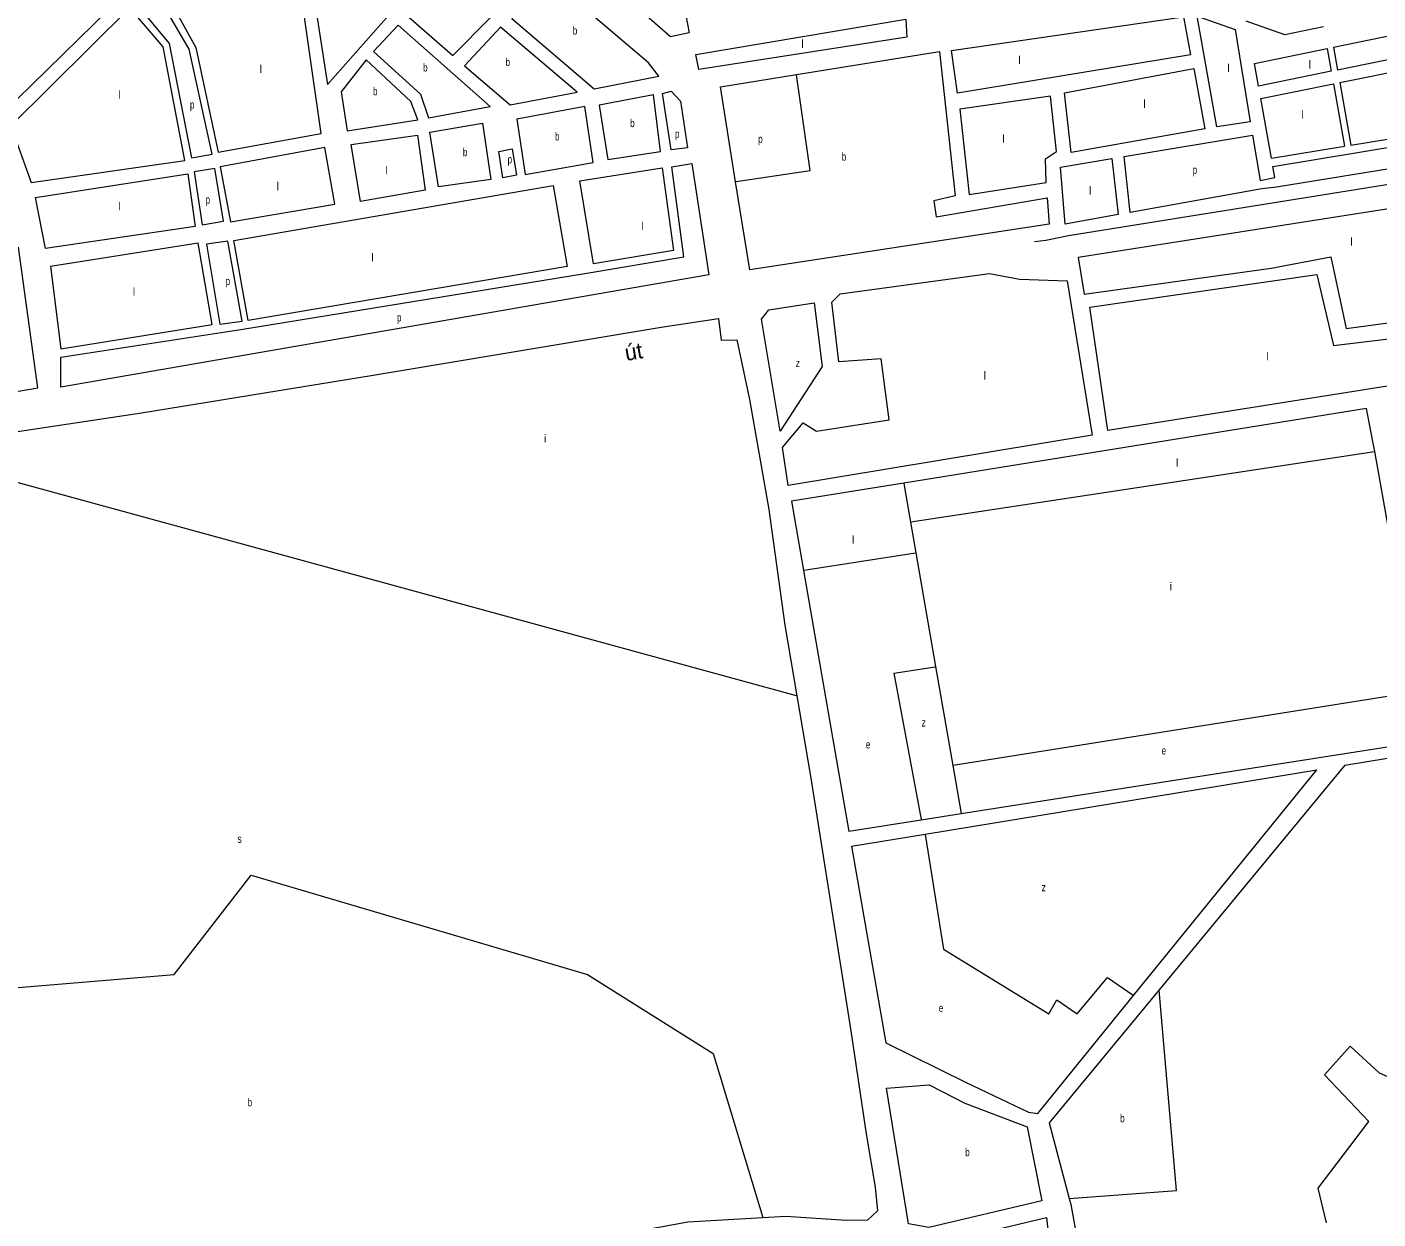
# Model space of a CAD drawing. Extents: x 639657 to 671642, y 222838 to 252123.
# Drawn here: x 655799 to 657488, y 238779 to 240268 of the extents above; entities that cross this region are included whole.
import ezdxf
from ezdxf.enums import TextEntityAlignment as Align

# ---------------------------------------------------------------- set-up
doc = ezdxf.new("R2010")
doc.units = 0
doc.header["$LTSCALE"] = 4
for name, color, linetype, lineweight in [('1', 7, 'Continuous', 13), ('21', 7, 'Continuous', 13), ('57', 7, 'Continuous', 35)]:
    doc.layers.add(name, color=color, linetype=linetype, lineweight=lineweight)
doc.layers.add('22', color=7, linetype='Continuous')
doc.layers.add('7', color=7, linetype='Continuous')

msp = doc.modelspace()

# ---------------------------------------------------------------- linework, layer by layer
at = {"layer": '1'}
for p, q in [((657440.128, 240199.175), (657810.98, 240273.89)), ((657432.386, 240243.339), (657437.407, 240214.696)), ((657424.384, 240241.691), (657429.422, 240213.067)), ((657429.422, 240213.067), (657338.5, 240194.51)), ((657432.149, 240197.567), (657445.911, 240119.373)), ((657440.128, 240199.175), (657453.886, 240120.68)), ((657356.452, 240094.294), (657868.995, 240179.025)), ((657453.886, 240120.68), (657863.625, 240187.808)), ((657354.638, 240104.42), (657445.911, 240119.373)), ((656620.345, 239981.002), (656605.174, 240093.516)), ((657358.975, 240080.212), (657356.452, 240094.294)), ((657340.768, 240076.569), (657358.975, 240080.212)), ((657532.85, 239461.56), (657483.794, 239737.856)), ((657446.404, 239345.829), (657548.961, 239362.665)), ((657076.74, 238898.92), (657101.809, 238804.075))]:
    msp.add_line(p, q, dxfattribs=at)
for points in [[(656038.26, 240112.12), (656167.07, 240135.24), (656138.48, 240333.32), (656161.37, 240359.31), (656024.31, 240480.17), (655954.37, 240424.76), (656018.37, 240359.19), (656046.1, 240384.68), (656055.85, 240376.7), (656017.48, 240338.22), (655942.63, 240414.45), (655887.738, 240364.976), (655929.677, 240318.542), (655946.632, 240334.615), (655986.76, 240284.75), (656010.24, 240243.03)], [(656184.46, 240361.66), (656331.27, 240232.83), (656378.16, 240279.98), (656227.04, 240410.92)], [(655875.92, 240357.99), (655708.83, 240222.76), (655766.91, 240158.75), (655921.49, 240310.54)], [(656155.79, 240320.57), (656174.61, 240196.57), (656251.27, 240283.21), (656174.37, 240347.6)], [(656004.633, 240105.124), (656030.511, 240109.589), (656001.956, 240240.854), (655977.863, 240281.93), (655951.986, 240314.077), (655935.924, 240297.111), (655976.971, 240247.998)], [(656405.05, 240279.13), (656507.95, 240191.31), (656589.112, 240206.922), (656575.95, 240223.59), (656454.63, 240326.84)], [(655778.86, 240144.88), (655804.2, 240074.15), (655996.42, 240101.56), (655969.38, 240243.76), (655927.56, 240292.32)], [(656635.19, 240233.93), (656897.56, 240278.06), (656899.09, 240255.92), (656638.91, 240215.52)], [(657253.48, 240233.63), (656962.15, 240185.75), (656954.81, 240239.13), (657244.73, 240281.34)], [(657328.13, 240149.82), (657286.25, 240143.56), (657261.68, 240282.1), (657309.54, 240265.2)], [(656263.2, 240270.95), (656232.31, 240237.91), (656291.07, 240184.56), (656301.02, 240154.78), (656378.05, 240169.26)], [(656345.89, 240220.05), (656403.3, 240171.08), (656487.03, 240186.83), (656391.17, 240268.26)], [(656191.89, 240187.58), (656199.3, 240138.74), (656287.58, 240152.39), (656279.08, 240175.42), (656223.26, 240227.62)], [(657271.62, 240141.02), (657104.21, 240111.69), (657095.9, 240186.2), (657257.53, 240216.72)], [(656582.3, 240183.66), (656514.55, 240170.71), (656525.36, 240103.04), (656591.15, 240112.74)], [(656604.282, 240188.17), (656615.882, 240175.669), (656624.805, 240117.626), (656604.282, 240114.947), (656593.574, 240185.491)], [(656976.79, 240059.18), (657073.17, 240074.14), (657072.1, 240103.6), (657086, 240112.86), (657078.41, 240182.13), (656965.1, 240165.7)], [(656496.41, 240169.15), (656411.52, 240153.42), (656421.79, 240084.17), (656507.01, 240099.13)], [(656378.84, 240077.9), (656313.58, 240068.52), (656302.53, 240136.89), (656368.56, 240148.22)], [(656297, 240064.73), (656215.99, 240050.2), (656204.29, 240121.58), (656287.23, 240133.11)], [(656183.98, 240046.91), (656171.63, 240117.68), (656040.83, 240093.74), (656053.39, 240025.07)], [(656394.01, 240079.98), (656388.77, 240112.89), (656405.81, 240116.18), (656411.06, 240083.12)], [(656008.202, 240087.265), (656018.018, 240021.185), (656044.788, 240025.65), (656034.08, 240091.729)], [(656593.21, 240092.6), (656607.26, 239989.3), (656507.11, 239972.54), (656490.14, 240076.14)], [(657163.16, 240034.04), (657097, 240022.12), (657091.21, 240093.29), (657155.14, 240103.9)], [(656009.57, 240019.09), (655822.49, 239991.56), (655809.74, 240055.38), (656000.17, 240085.06)], [(656457.07, 240070.25), (656474.44, 239969.12), (656075.79, 239901.79), (656057.55, 240001.73)], [(657517.06, 240043.8), (657113.18, 239980.21), (657120.7, 239934.36), (657354.17, 239967.04), (657429.04, 239981.26), (657447.95, 239891.45), (657611.68, 239913.87), (657622.24, 239840.98), (657753.5, 239864.1), (657733.93, 239967.47), (657534.98, 239936.3)], [(656030.77, 239896.55), (656013.18, 239998.14), (655828.39, 239969.12), (655841.28, 239866.03)], [(657130.48, 239758.36), (656750.54, 239695.19), (656743.44, 239742.83), (656769.54, 239773.57), (656785.91, 239763.23), (656876.91, 239777.31), (656866.94, 239853.9), (656813.84, 239849.9), (656804.99, 239924.36), (656815.48, 239934.84), (657002.37, 239960.44), (657039.63, 239953.3), (657099.33, 239951.03)], [(657150.21, 239764.23), (657127.55, 239918.42), (657411.34, 239959), (657432.31, 239870.39), (657587.71, 239889.26), (657594.46, 239834.38)], [(656740.78, 239763.18), (656717.39, 239903.38), (656726.24, 239914.88), (656782.97, 239923.82), (656793.03, 239844.01)], [(657067.58, 238801.14), (656926.35, 238767.97), (656900.96, 238772.58), (656873.43, 238942.25), (656926.71, 238946.24), (656971.35, 238923.17), (657049.41, 238893.85)]]:
    msp.add_lwpolyline(points, close=True, dxfattribs=at)
for points in [[(656608.126, 240358.923), (656626.69, 240261.1), (656603.62, 240256.07), (656554.807, 240298.761)], [(657432.386, 240243.339), (657785.24, 240315.98), (657801.71, 240289.05), (657437.407, 240214.696)], [(657419.645, 240268.617), (657371.42, 240258.88), (657323.033, 240275.963)], [(656761.154, 240209.071), (656939.76, 240237.93), (656959.2, 240057.24), (656932.75, 240051.25), (656935.7, 240031.2), (657074.49, 240055.14)], [(657338.5, 240194.51), (657333.4, 240222.96), (657424.384, 240241.691)], [(656684.924, 240075.134), (656665.9, 240193.68), (656761.154, 240209.071)], [(657354.638, 240104.42), (657341.23, 240179.25), (657432.149, 240197.567)], [(657868.995, 240179.025), (657884.63, 240153.46), (657361.09, 240068.41)], [(657170.78, 240106.5), (657330.96, 240133.09), (657340.768, 240076.569)], [(656605.174, 240093.516), (656630.159, 240097.981), (656651.575, 239958.679), (655841.338, 239818.484), (655841.338, 239855.988), (656068.884, 239890.813), (656496.311, 239960.464), (656620.345, 239981.002)], [(657361.09, 240068.41), (657342.54, 240066.36), (657178.26, 240036.76), (657170.78, 240106.5)], [(657074.49, 240055.14), (657076.67, 240022.23), (656702.61, 239964.93), (656684.924, 240075.134)], [(655362.97, 239740.21), (655812.87, 239817.26), (655788.671, 239993.339)], [(656050.142, 240000.647), (656023.372, 239997.075), (656040.326, 239897.064)], [(656040.326, 239897.064), (656067.989, 239900.635), (656050.142, 240000.647)], [(655641.374, 239739.019), (655742.56, 239756.09), (655942.24, 239786.31), (656231.77, 239833.27), (656591.9, 239893.28), (656663.64, 239904.19), (656667, 239876.87), (656686.34, 239877.35), (656702.17, 239803.06), (656726.56, 239665.58), (656746.3, 239520.99), (656761.439, 239432.394)], [(657483.794, 239737.856), (657481.56, 239750.44), (657473.29, 239791.79), (656894.987, 239698.507)], [(656894.987, 239698.507), (656754.59, 239675.86), (656769.667, 239589.325), (656826.504, 239263.102)], [(656761.439, 239432.394), (656779.03, 239329.44), (656828.84, 239013.66), (656848.17, 238885.18), (656859.52, 238818.3), (656862.4, 238788.82), (656849.8, 238777.22), (656822.95, 238776.55), (656747.59, 238781.66), (656718.907, 238780.019)], [(657536.867, 239437.967), (657547.471, 239375.673), (656966.961, 239285.033), (656916.974, 239277.228), (656826.504, 239263.102)], [(656829.729, 239244.592), (656921.733, 239259.696), (657411.457, 239340.091)], [(656829.729, 239244.592), (656872.54, 238998.87), (656972.3, 238949.52), (657051.15, 238912.26), (657062.48, 238910.39), (657182.229, 239057.839), (657411.457, 239340.091)], [(657446.404, 239345.829), (657214.229, 239065.139), (657076.74, 238898.92)], [(656718.907, 238780.019), (656625.27, 238774.66), (656525.23, 238756.25), (656405.61, 238726.41), (656315.33, 238704.82), (656225.69, 238679.49), (656149.4, 238649.6), (656114.03, 238632.12), (656063.82, 238641.61), (656057.49, 238615.66), (655994.43, 238601.74), (655937.14, 238593.33), (655873.63, 238597.66), (655808.27, 238611.08), (655751.82, 238633.86), (655717.51, 238651.81), (655630.69, 238707.14), (655588.91, 238744.79), (655569.62, 238764.19), (655583.18, 238780.65), (655604.36, 238783.92), (655596.58, 238911.02)], [(657101.809, 238804.075), (657103.74, 238796.77), (657121.47, 238700.15), (657236.02, 238696.55), (657417.718, 238621.02)], [(656952.53, 238751.83), (657073.58, 238780.36), (657081.17, 238714.18)]]:
    msp.add_lwpolyline(points, dxfattribs=at)
at = {"layer": '21'}
for points in [[(656684.924, 240075.134), (656685.424, 240075.209), (656778.288, 240089.05), (656761.225, 240208.571), (656761.154, 240209.071)], [(656761.439, 239432.394), (656760.938, 239432.531), (655641.874, 239738.882), (655641.374, 239739.019)], [(656903.481, 239649.711), (656903.981, 239649.787), (657483.294, 239737.78), (657483.794, 239737.856)], [(656894.987, 239698.507), (656895.074, 239698.007), (656903.481, 239649.711), (656910.154, 239611.378), (656934.941, 239468.98), (656956.425, 239345.559)], [(656769.667, 239589.325), (656770.167, 239589.403), (656909.654, 239611.3), (656910.154, 239611.378)], [(656882.557, 239460.915), (656934.441, 239468.903), (656934.941, 239468.98)], [(656882.557, 239460.915), (656916.88, 239277.728), (656916.974, 239277.228)], [(656956.425, 239345.559), (656956.925, 239345.639), (657536.534, 239437.914), (657536.867, 239437.967)], [(656956.425, 239345.559), (656966.874, 239285.533), (656966.961, 239285.033)], [(656921.733, 239259.696), (656921.813, 239259.196), (656944.82, 239115.945), (657076.491, 239034.859), (657086.62, 239052.596), (657111.941, 239034.859), (657149.924, 239080.469), (657181.729, 239058.189), (657182.229, 239057.839)], [(655596.58, 238911.02), (655597.08, 238911.111), (655727.489, 238934.76), (655737.617, 239063.99), (655983.235, 239084.262), (656079.456, 239208.425), (656499.792, 239084.262), (656656.785, 238985.439), (656718.756, 238780.519), (656718.907, 238780.019)], [(657101.809, 238804.075), (657236.016, 238814.406), (657214.272, 239064.638), (657214.229, 239065.139)], [(657423.395, 238773.863), (657413.267, 238816.94), (657476.57, 238900.559), (657420.863, 238958.84), (657453.195, 238994.43), (657489.231, 238961.374), (657575.324, 238923.365), (657704.463, 238872.686), (657876.649, 238839.745), (658048.835, 238824.541), (658129.864, 238832.143), (658231.15, 238857.483), (658296.986, 238862.55), (658370.418, 238837.211), (658388.143, 238819.473), (658393.207, 238781.464), (658398.272, 238758.659)]]:
    msp.add_lwpolyline(points, dxfattribs=at)
at = {"layer": '57', "lineweight": 13}
msp.add_lwpolyline([(660000, 240579.681), (659729.838, 240508.731), (659154.006, 240361.508), (658884.968, 240296.195), (658468.447, 240220.857), (658221.071, 240180.865), (657516.999, 240073.954), (657101.087, 240007.445), (657072.54, 240001.797), (657058.514, 240000)], dxfattribs=at)

# ---------------------------------------------------------------- texts
at = {"layer": '22'}
msp.add_text('út', height=20, rotation=9.58, dxfattribs=at).set_placement((656559.033, 239852.84), align=Align.CENTER)
at = {"layer": '7'}
for s, width, p in [('b', 0.75, (656481.402, 240259.075)), ('b', 0.75, (656397.353, 240219.67)), ('b', 0.75, (656294.348, 240212.865)), ('b', 0.75, (656231.67, 240183.18)), ('p', 0.75, (656002.844, 240166.476)), ('b', 0.75, (656553.125, 240143.35)), ('b', 0.75, (656459.165, 240126.66)), ('p', 0.75, (656609.183, 240129.906)), ('p', 0.75, (656713.141, 240123.614)), ('b', 0.75, (656344.055, 240107.015)), ('b', 0.75, (656817.575, 240101.43)), ('p', 0.75, (656399.906, 240098.08)), ('p', 0.75, (657256.206, 240084.925)), ('p', 0.75, (656022.476, 240047.712)), ('p', 0.75, (656047.461, 239945.914)), ('p', 0.75, (656261.621, 239900.373)), ('z', 0.8, (656760.04, 239843.5)), ('z', 0.8, (656917.373, 239394.157)), ('e', 0.75, (656847.733, 239366.762)), ('e', 0.75, (657217.426, 239359.16)), ('s', 0.8, (656062.339, 239248.76)), ('z', 0.8, (657067.388, 239188.246)), ('e', 0.75, (656938.89, 239037.35)), ('b', 0.75, (656075, 238919.349)), ('b', 0.75, (657165.601, 238899.539)), ('b', 0.75, (656971.928, 238857.105))]:
    msp.add_text(s, height=10, dxfattribs=dict(at, width=width)).set_placement(p)
for s, p in [('l', (656767.039, 240242.322)), ('l', (657038.329, 240222.157)), ('l', (657401.135, 240216.571)), ('l', (656089.822, 240210.921)), ('l', (657299.55, 240212.102)), ('l', (655913.14, 240178.775)), ('l', (657194.615, 240167.418)), ('l', (657392.205, 240154.013)), ('l', (657018.235, 240123.85)), ('l', (656246.872, 240084.121)), ('l', (656111.238, 240064.475)), ('l', (657126.519, 240059.058)), ('l', (655913.14, 240039.472)), ('l', (656566.798, 240014.672)), ('l', (657453.112, 239995.055)), ('l', (656229.496, 239975.382)), ('l', (655931.458, 239932.52)), ('l', (657348.028, 239851.888)), ('l', (656994.793, 239827.815)), ('i', (656445.317, 239749.263)), ('l', (657235.347, 239718.856)), ('l', (656830.203, 239622.567)), ('i', (657227.554, 239564.409))]:
    msp.add_text(s, height=10, dxfattribs=at).set_placement(p)

doc.saveas('drawing.dxf')
